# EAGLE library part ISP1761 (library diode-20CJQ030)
Philips Semiconductor's ISP1761 Hi-Speed Universal Serial Bus On-The-Go controller Description: The ISP1761 is a single-chip Hi-Speed Universal Serial Bus (USB) On-The-Go (OTG) Controller integrated with the Advanced Philips Slave Host Controller and the Philips ISP1582 Peripheral Controller. The Hi-Speed USB Host Controller and Peripheral Controller comply to Universal Serial Bus Specification Rev. 2.0 and support data transfer speeds of up to 480 Mbit/s. The Enhanced Host Controller Interface (EHCI) core implemented in the Host Controller is adapted from Enhanced Host Controller Interface Specification for Universal Serial Bus Rev. 1.0. The OTG Controller is compliant with On-The-Go Supplement to the USB Specification Rev. 1.0a. The ISP1761 has three USB ports. Port 1 can be configured to function as a downstream port, an upstream port or an OTG port; ports 2 and 3 are always configured as downstream ports. The OTG port can switch its role from host to peripheral, and peripheral to host. The OTG port can become a host through the Host Negotiation Protocol (HNP) as specified in the OTG supplement. Features: Compliant with Universal Serial Bus Specification Rev. 2.0; supporting data transfer at high-speed (480 Mbit/s), full-speed (12 Mbit/s) and low-speed (1.5 Mbit/s) Integrated Transaction Translator (TT) for Original USB (full-speed and low-speed) peripheral support Three USB ports that support three operational modes: - Mode 1: Port 1 is an OTG Controller port, and ports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
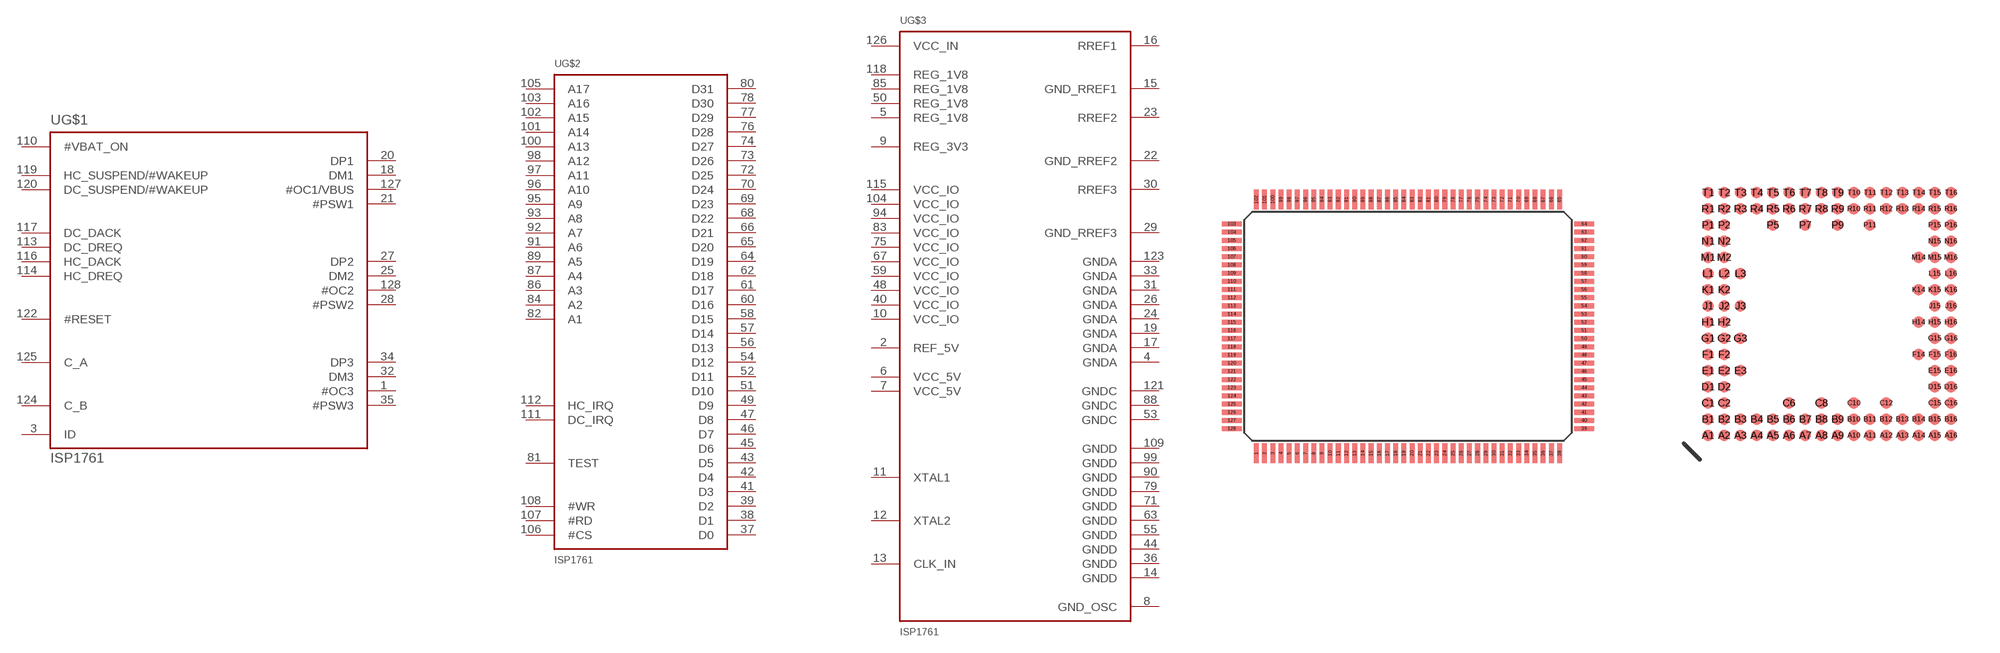
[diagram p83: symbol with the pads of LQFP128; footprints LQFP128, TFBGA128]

Designator prefix U; gates G$1=ISP1761_CTRL G$2=ISP1761_MEM G$3=ISP1761_PWR

## ISP1761LQFP  [LQFP128]
1  G$1:#OC3  in
2  G$3:REF_5V  pwr
3  G$1:ID  in
4  G$3:GNDA  pwr
5  G$3:REG_1V8  pwr
6  G$3:VCC_5V  pwr
7  G$3:VCC_5V  pwr
8  G$3:GND_OSC  pwr
9  G$3:REG_3V3  pwr
10  G$3:VCC_IO  pwr
11  G$3:XTAL1  pwr
12  G$3:XTAL2  pwr
13  G$3:CLK_IN  pwr
14  G$3:GNDD  pwr
15  G$3:GND_RREF1  pwr
16  G$3:RREF1  pwr
17  G$3:GNDA  pwr
18  G$1:DM1
19  G$3:GNDA  pwr
20  G$1:DP1
21  G$1:#PSW1  out
22  G$3:GND_RREF2  pwr
23  G$3:RREF2  pwr
24  G$3:GNDA  pwr
25  G$1:DM2
26  G$3:GNDA  pwr
27  G$1:DP2
28  G$1:#PSW2  out
29  G$3:GND_RREF3  pwr
30  G$3:RREF3  pwr
31  G$3:GNDA  pwr
32  G$1:DM3
33  G$3:GNDA  pwr
34  G$1:DP3
35  G$1:#PSW3  out
36  G$3:GNDD  pwr
37  G$2:D0
38  G$2:D1
39  G$2:D2
40  G$3:VCC_IO  pwr
41  G$2:D3
42  G$2:D4
43  G$2:D5
44  G$3:GNDD  pwr
45  G$2:D6
46  G$2:D7
47  G$2:D8
48  G$3:VCC_IO  pwr
49  G$2:D9
50  G$3:REG_1V8  pwr
51  G$2:D10
52  G$2:D11
53  G$3:GNDC  pwr
54  G$2:D12
55  G$3:GNDD  pwr
56  G$2:D13
57  G$2:D14
58  G$2:D15
59  G$3:VCC_IO  pwr
60  G$2:D16
61  G$2:D17
62  G$2:D18
63  G$3:GNDD  pwr
64  G$2:D19
65  G$2:D20
66  G$2:D21
67  G$3:VCC_IO  pwr
68  G$2:D22
69  G$2:D23
70  G$2:D24
71  G$3:GNDD  pwr
72  G$2:D25
73  G$2:D26
74  G$2:D27
75  G$3:VCC_IO  pwr
76  G$2:D28
77  G$2:D29
78  G$2:D30
79  G$3:GNDD  pwr
80  G$2:D31
81  G$2:TEST  pas
82  G$2:A1  in
83  G$3:VCC_IO  pwr
84  G$2:A2  in
85  G$3:REG_1V8  pwr
86  G$2:A3  in
87  G$2:A4  in
88  G$3:GNDC  pwr
89  G$2:A5  in
90  G$3:GNDD  pwr
91  G$2:A6  in
92  G$2:A7  in
93  G$2:A8  in
94  G$3:VCC_IO  pwr
95  G$2:A9  in
96  G$2:A10  in
97  G$2:A11  in
98  G$2:A12  in
99  G$3:GNDD  pwr
100  G$2:A13  in
101  G$2:A14  in
102  G$2:A15  in
103  G$2:A16  in
104  G$3:VCC_IO  pwr
105  G$2:A17  in
106  G$2:#CS  in
107  G$2:#RD  in
108  G$2:#WR  in
109  G$3:GNDD  pwr
110  G$1:#VBAT_ON  out
111  G$2:DC_IRQ  out
112  G$2:HC_IRQ  out
113  G$1:DC_DREQ  out
114  G$1:HC_DREQ  out
115  G$3:VCC_IO  pwr
116  G$1:HC_DACK  in
117  G$1:DC_DACK  in
118  G$3:REG_1V8  pwr
119  G$1:HC_SUSPEND/#WAKEUP
120  G$1:DC_SUSPEND/#WAKEUP
121  G$3:GNDC  pwr
122  G$1:#RESET  in
123  G$3:GNDA  pwr
124  G$1:C_B
125  G$1:C_A
126  G$3:VCC_IN  pwr
127  G$1:#OC1/VBUS  in
128  G$1:#OC2  in

## ISP1761TFBGA  [TFBGA128]
A1  G$3:GNDA  pwr
A2  G$3:REF_5V  pwr
A3  G$1:#OC2  in
A4  G$3:VCC_IN  pwr
A5  G$1:C_B
A6  G$3:GNDC  pwr
A7  G$1:HC_SUSPEND/#WAKEUP
A8  G$1:HC_DACK  in
A9  G$1:DC_DREQ  out
A10  G$2:DC_IRQ  out
A11  G$3:GNDD  pwr
A12  G$2:#CS  in
A13  G$2:A16  in
A14  G$2:A15  in
A15  G$2:A13  in
A16  G$3:GNDD  pwr
B1  G$3:REG_1V8  pwr
B2  G$1:ID  in
B3  G$1:#OC1/VBUS  in
B4  G$1:C_A
B5  G$3:GNDA  pwr
B6  G$1:#RESET  in
B7  G$3:REG_1V8  pwr
B8  G$1:DC_DACK  in
B9  G$1:HC_DREQ  out
B10  G$2:HC_IRQ  out
B11  G$2:#WR  in
B12  G$2:#RD  in
B13  G$3:VCC_IO  pwr
B14  G$2:A14  in
B15  G$2:A12  in
B16  G$2:A11  in
C1  G$3:VCC_5V  pwr
C2  G$1:#OC3  in
C6  G$1:DC_SUSPEND/#WAKEUP
C8  G$3:VCC_IO  pwr
C10  G$1:#VBAT_ON  out
C12  G$2:A17  in
C15  G$2:A10  in
C16  G$2:A9  in
D1  G$3:REG_3V3  pwr
D2  G$3:VCC_5V  pwr
D15  G$3:VCC_IO  pwr
D16  G$2:A8  in
E1  G$3:XTAL1  pwr
E2  G$3:VCC_IO  pwr
E3  G$3:GND_OSC  pwr
E15  G$2:A7  in
E16  G$3:GNDD  pwr
F1  G$3:CLK_IN  pwr
F2  G$3:XTAL2  pwr
F14  G$2:A6  in
F15  G$2:A5  in
F16  G$2:A4  in
G1  G$3:RREF1  pwr
G2  G$3:GND_RREF1  pwr
G3  G$3:GNDD  pwr
G15  G$3:GNDC  pwr
G16  G$3:REG_1V8  pwr
H1  G$1:DM1
H2  G$3:GNDA  pwr
H14  G$2:A3  in
H15  G$2:A2  in
H16  G$2:A1  in
J1  G$1:#PSW1  out
J2  G$1:DP1
J3  G$3:GNDA  pwr
J15  G$3:VCC_IO  pwr
J16  G$2:TEST  pas
K1  G$3:RREF2  pwr
K2  G$3:GND_RREF2  pwr
K14  G$2:D31
K15  G$3:GNDD  pwr
K16  G$2:D30
L1  G$1:DM2
L2  G$3:GNDA  pwr
L3  G$3:GNDA  pwr
L15  G$2:D29
L16  G$2:D28
M1  G$1:#PSW2  out
M2  G$1:DP2
M14  G$3:VCC_IO  pwr
M15  G$2:D26
M16  G$2:D27
N1  G$3:RREF3  pwr
N2  G$3:GND_RREF3  pwr
N15  G$2:D25
N16  G$3:GNDD  pwr
P1  G$1:DM3
P2  G$3:GNDA  pwr
P5  G$2:D3
P7  G$2:D7
P9  G$2:D10
P11  G$2:D13
P15  G$3:VCC_IO  pwr
P16  G$2:D24
R1  G$1:DP3
R2  G$3:GNDA  pwr
R3  G$2:D0
R4  G$2:D2
R5  G$2:D5
R6  G$2:D6
R7  G$3:VCC_IO  pwr
R8  G$3:REG_1V8  pwr
R9  G$3:GNDC  pwr
R10  G$3:GNDD  pwr
R11  G$2:D15
R12  G$2:D16
R13  G$2:D18
R14  G$3:GNDD  pwr
R15  G$2:D21
R16  G$2:D23
T1  G$1:#PSW3  out
T2  G$3:GNDD  pwr
T3  G$2:D1
T4  G$3:VCC_IO  pwr
T5  G$2:D4
T6  G$3:GNDD  pwr
T7  G$2:D8
T8  G$2:D9
T9  G$2:D11
T10  G$2:D12
T11  G$2:D14
T12  G$3:VCC_IO  pwr
T13  G$2:D17
T14  G$2:D19
T15  G$2:D20
T16  G$2:D22

## Footprint LQFP128 (pad centres in mm)
smd 0.3 x 1.2: 1 -9.25,-7.75; 2 -8.75,-7.75; 3 -8.25,-7.75; 4 -7.75,-7.75; 5 -7.25,-7.75; 6 -6.75,-7.75; 7 -6.25,-7.75; 8 -5.75,-7.75; 9 -5.25,-7.75; 10 -4.75,-7.75; 11 -4.25,-7.75; 12 -3.75,-7.75; 13 -3.25,-7.75; 14 -2.75,-7.75; 15 -2.25,-7.75; 16 -1.75,-7.75; 17 -1.25,-7.75; 18 -0.75,-7.75; 19 -0.25,-7.75; 20 0.25,-7.75; 21 0.75,-7.75; 22 1.25,-7.75; 23 1.75,-7.75; 24 2.25,-7.75; 25 2.75,-7.75; 26 3.25,-7.75; 27 3.75,-7.75; 28 4.25,-7.75; 29 4.75,-7.75; 30 5.25,-7.75; 31 5.75,-7.75; 32 6.25,-7.75; 33 6.75,-7.75; 34 7.25,-7.75; 35 7.75,-7.75; 36 8.25,-7.75; 37 8.75,-7.75; 38 9.25,-7.75; 65 9.25,7.75; 66 8.75,7.75; 67 8.25,7.75; 68 7.75,7.75; 69 7.25,7.75; 70 6.75,7.75; 71 6.25,7.75; 72 5.75,7.75; 73 5.25,7.75; 74 4.75,7.75; 75 4.25,7.75; 76 3.75,7.75; 77 3.25,7.75; 78 2.75,7.75; 79 2.25,7.75; 80 1.75,7.75; 81 1.25,7.75; 82 0.75,7.75; 83 0.25,7.75; 84 -0.25,7.75; 85 -0.75,7.75; 86 -1.25,7.75; 87 -1.75,7.75; 88 -2.25,7.75; 89 -2.75,7.75; 90 -3.25,7.75; 91 -3.75,7.75; 92 -4.25,7.75; 93 -4.75,7.75; 94 -5.25,7.75; 95 -5.75,7.75; 96 -6.25,7.75; 97 -6.75,7.75; 98 -7.25,7.75; 99 -7.75,7.75; 100 -8.25,7.75; 101 -8.75,7.75; 102 -9.25,7.75
smd 1.2 x 0.3: 39 10.75,-6.25; 40 10.75,-5.75; 41 10.75,-5.25; 42 10.75,-4.75; 43 10.75,-4.25; 44 10.75,-3.75; 45 10.75,-3.25; 46 10.75,-2.75; 47 10.75,-2.25; 48 10.75,-1.75; 49 10.75,-1.25; 50 10.75,-0.75; 51 10.75,-0.25; 52 10.75,0.25; 53 10.75,0.75; 54 10.75,1.25; 55 10.75,1.75; 56 10.75,2.25; 57 10.75,2.75; 58 10.75,3.25; 59 10.75,3.75; 60 10.75,4.25; 61 10.75,4.75; 62 10.75,5.25; 63 10.75,5.75; 64 10.75,6.25; 103 -10.75,6.25; 104 -10.75,5.75; 105 -10.75,5.25; 106 -10.75,4.75; 107 -10.75,4.25; 108 -10.75,3.75; 109 -10.75,3.25; 110 -10.75,2.75; 111 -10.75,2.25; 112 -10.75,1.75; 113 -10.75,1.25; 114 -10.75,0.75; 115 -10.75,0.25; 116 -10.75,-0.25; 117 -10.75,-0.75; 118 -10.75,-1.25; 119 -10.75,-1.75; 120 -10.75,-2.25; 121 -10.75,-2.75; 122 -10.75,-3.25; 123 -10.75,-3.75; 124 -10.75,-4.25; 125 -10.75,-4.75; 126 -10.75,-5.25; 127 -10.75,-5.75; 128 -10.75,-6.25

## Footprint TFBGA128 (pad centres in mm)
smd 0.35 x 0.35: A1 -3.75,-3.75; A2 -3.25,-3.75; A3 -2.75,-3.75; A4 -2.25,-3.75; A5 -1.75,-3.75; A6 -1.25,-3.75; A7 -0.75,-3.75; A8 -0.25,-3.75; A9 0.25,-3.75; A10 0.75,-3.75; A11 1.25,-3.75; A12 1.75,-3.75; A13 2.25,-3.75; A14 2.75,-3.75; A15 3.25,-3.75; A16 3.75,-3.75; B1 -3.75,-3.25; B2 -3.25,-3.25; B3 -2.75,-3.25; B4 -2.25,-3.25; B5 -1.75,-3.25; B6 -1.25,-3.25; B7 -0.75,-3.25; B8 -0.25,-3.25; B9 0.25,-3.25; B10 0.75,-3.25; B11 1.25,-3.25; B12 1.75,-3.25; B13 2.25,-3.25; B14 2.75,-3.25; B15 3.25,-3.25; B16 3.75,-3.25; C1 -3.75,-2.75; C2 -3.25,-2.75; C6 -1.25,-2.75; C8 -0.25,-2.75; C10 0.75,-2.75; C12 1.75,-2.75; C15 3.25,-2.75; C16 3.75,-2.75; D1 -3.75,-2.25; D2 -3.25,-2.25; D15 3.25,-2.25; D16 3.75,-2.25; E1 -3.75,-1.75; E2 -3.25,-1.75; E3 -2.75,-1.75; E15 3.25,-1.75; E16 3.75,-1.75; F1 -3.75,-1.25; F2 -3.25,-1.25; F14 2.75,-1.25; F15 3.25,-1.25; F16 3.75,-1.25; G1 -3.75,-0.75; G2 -3.25,-0.75; G3 -2.75,-0.75; G15 3.25,-0.75; G16 3.75,-0.75; H1 -3.75,-0.25; H2 -3.25,-0.25; H14 2.75,-0.25; H15 3.25,-0.25; H16 3.75,-0.25; J1 -3.75,0.25; J2 -3.25,0.25; J3 -2.75,0.25; J15 3.25,0.25; J16 3.75,0.25; K1 -3.75,0.75; K2 -3.25,0.75; K14 2.75,0.75; K15 3.25,0.75; K16 3.75,0.75; L1 -3.75,1.25; L2 -3.25,1.25; L3 -2.75,1.25; L15 3.25,1.25; L16 3.75,1.25; M1 -3.75,1.75; M2 -3.25,1.75; M14 2.75,1.75; M15 3.25,1.75; M16 3.75,1.75; N1 -3.75,2.25; N2 -3.25,2.25; N15 3.25,2.25; N16 3.75,2.25; P1 -3.75,2.75; P2 -3.25,2.75; P5 -1.75,2.75; P7 -0.75,2.75; P9 0.25,2.75; P11 1.25,2.75; P15 3.25,2.75; P16 3.75,2.75; R1 -3.75,3.25; R2 -3.25,3.25; R3 -2.75,3.25; R4 -2.25,3.25; R5 -1.75,3.25; R6 -1.25,3.25; R7 -0.75,3.25; R8 -0.25,3.25; R9 0.25,3.25; R10 0.75,3.25; R11 1.25,3.25; R12 1.75,3.25; R13 2.25,3.25; R14 2.75,3.25; R15 3.25,3.25; R16 3.75,3.25; T1 -3.75,3.75; T2 -3.25,3.75; T3 -2.75,3.75; T4 -2.25,3.75; T5 -1.75,3.75; T6 -1.25,3.75; T7 -0.75,3.75; T8 -0.25,3.75; T9 0.25,3.75; T10 0.75,3.75; T11 1.25,3.75; T12 1.75,3.75; T13 2.25,3.75; T14 2.75,3.75; T15 3.25,3.75; T16 3.75,3.75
